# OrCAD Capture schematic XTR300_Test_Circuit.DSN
size A; title: XTR300, Industrial Analog Current/Voltage OUTPUT DRIVER; rev: 1.1; note: Datasheet: SBOS336C  EVM: N/A
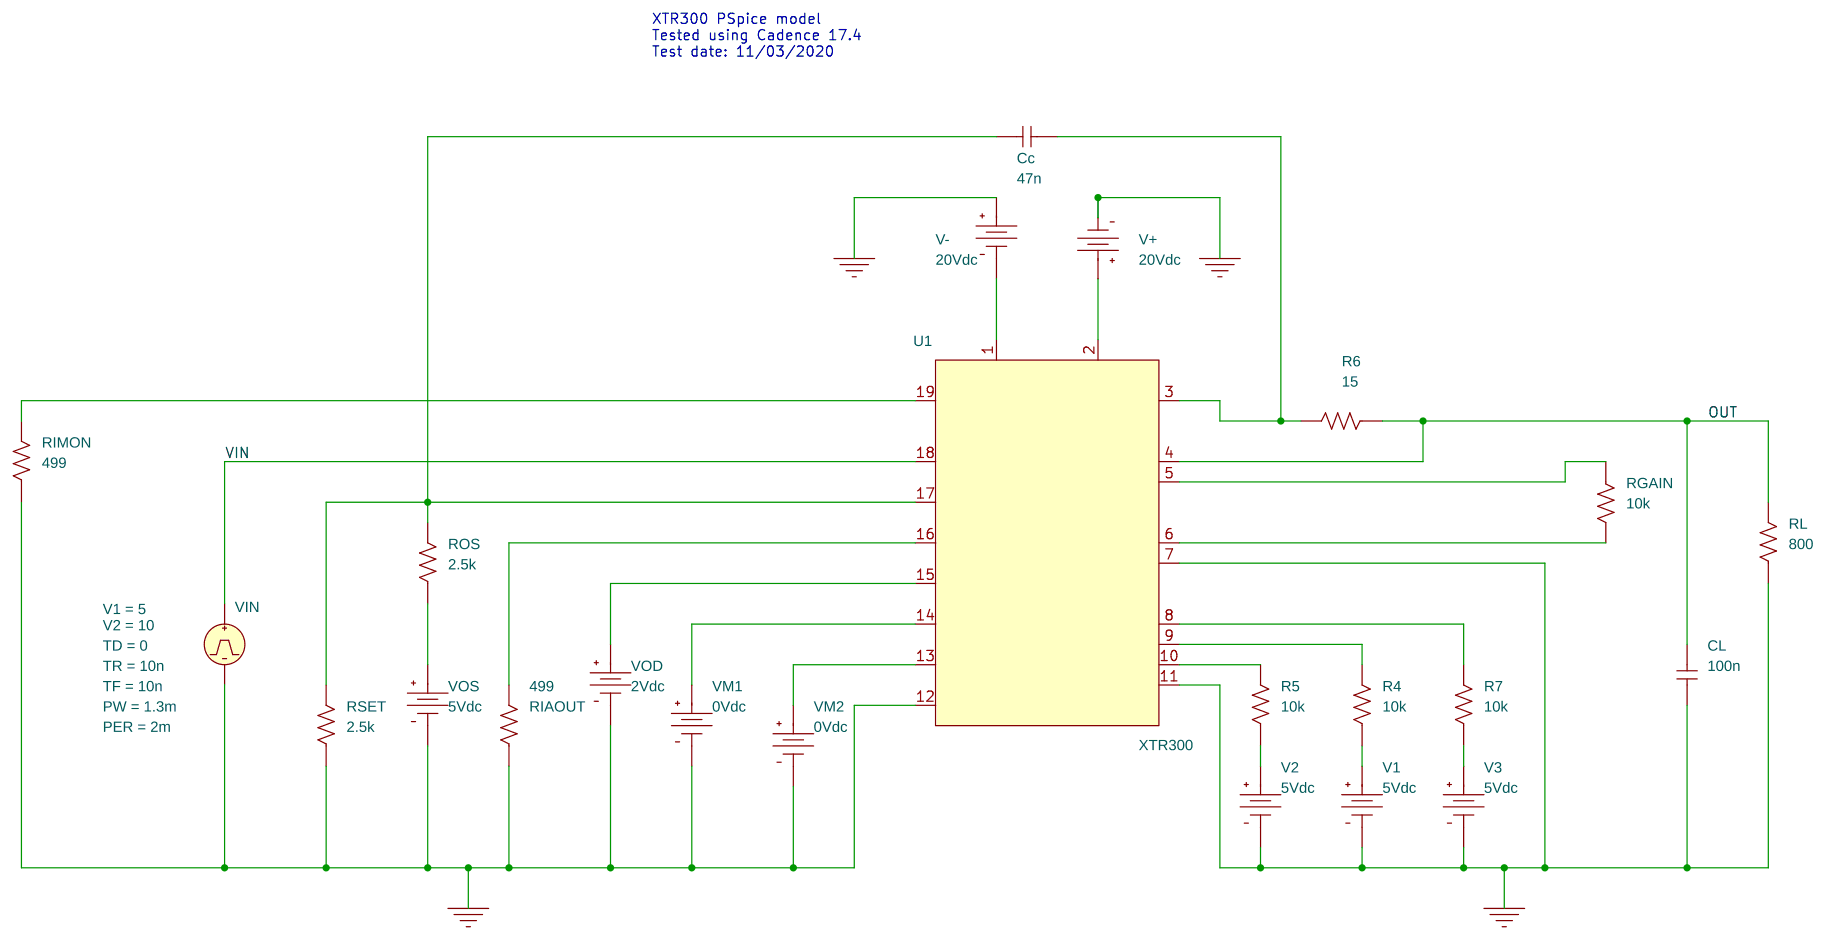
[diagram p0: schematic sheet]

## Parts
Cc  47n  [RAD/CK05]
CL  100n  [RAD/CK05]
R4  10k  [AX/RC05]
R5  10k  [AX/RC05]
R6  15  [AX/RC05]
R7  10k  [AX/RC05]
RGAIN  10k  [AX/RC05]
RIAOUT  499  [AX/RC05]
RIMON  499  [AX/RC05]
RL  800  [AX/RC05]
ROS  2.5k  [AX/RC05]
RSET  2.5k  [AX/RC05]
U1  XTR300
V1  VDC
V2  VDC
V3  VDC
V+  VDC
V-  VDC
VIN  VPULSE
VM1  VDC
VM2  VDC
VOD  VDC
VOS  VDC

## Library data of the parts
Cc CL = C
R4-R7 RGAIN RIAOUT RIMON RL ROS RSET = R
U1 = XTR300
V1-V3 VOS = VDC: DC: 5Vdc
V+ V- = VDC: DC: 20Vdc
VIN = VPULSE: PER: 2m; PW: 1.3m; TD: 0; TF: 10n; TR: 10n; V1: 5; V2: 10
VM1 VM2 = VDC: DC: 0Vdc
VOD = VDC: DC: 2Vdc

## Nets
VIN: U1.18(VIN) VIN.1(+)
0: CL.1 RIAOUT.1 RIMON.1 RL.1 RSET.1 U1.7(IA_IN-) U1.11(DGND) U1.12(GND) V1.1(-) V2.1(-) V3.1(-) V+.1(-) V-.0(+) VIN.2(-) VM1.1(-) VM2.1(-) VOD.1(-) VOS.1(-)
OUT: CL.2 R6.1 RL.2 U1.4(IA_IN+)
N39884: U1.2(V+) V+.0(+)
N40002: RIMON.2 U1.19(IMON)
N40149: Cc.1 ROS.2 RSET.2 U1.17(SET)
N40667: RIAOUT.2 U1.16(IAOUT)
N41148: U1.15(OD_N) VOD.0(+)
N41385: U1.14(M1) VM1.0(+)
N41424: U1.13(M2) VM2.0(+)
N43322: Cc.2 R6.2 U1.3(DRV)
N43697: RGAIN.1 U1.5(RG1)
N43709: RGAIN.2 U1.6(RG2)
N44093: R7.1 V3.0(+)
N44733: R5.2 U1.10(EFOT)
N44796: R5.1 V2.0(+)
N50887: R4.2 U1.9(EFLD)
N50984: R7.2 U1.8(EFCM)
N52223: ROS.1 VOS.0(+)
N53445: U1.1(V-) V-.1(-)
N56234: R4.1 V1.0(+)

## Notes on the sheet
- XTR300 PSpice model
  Tested using Cadence 17.4
  Test date: 11/03/2020
